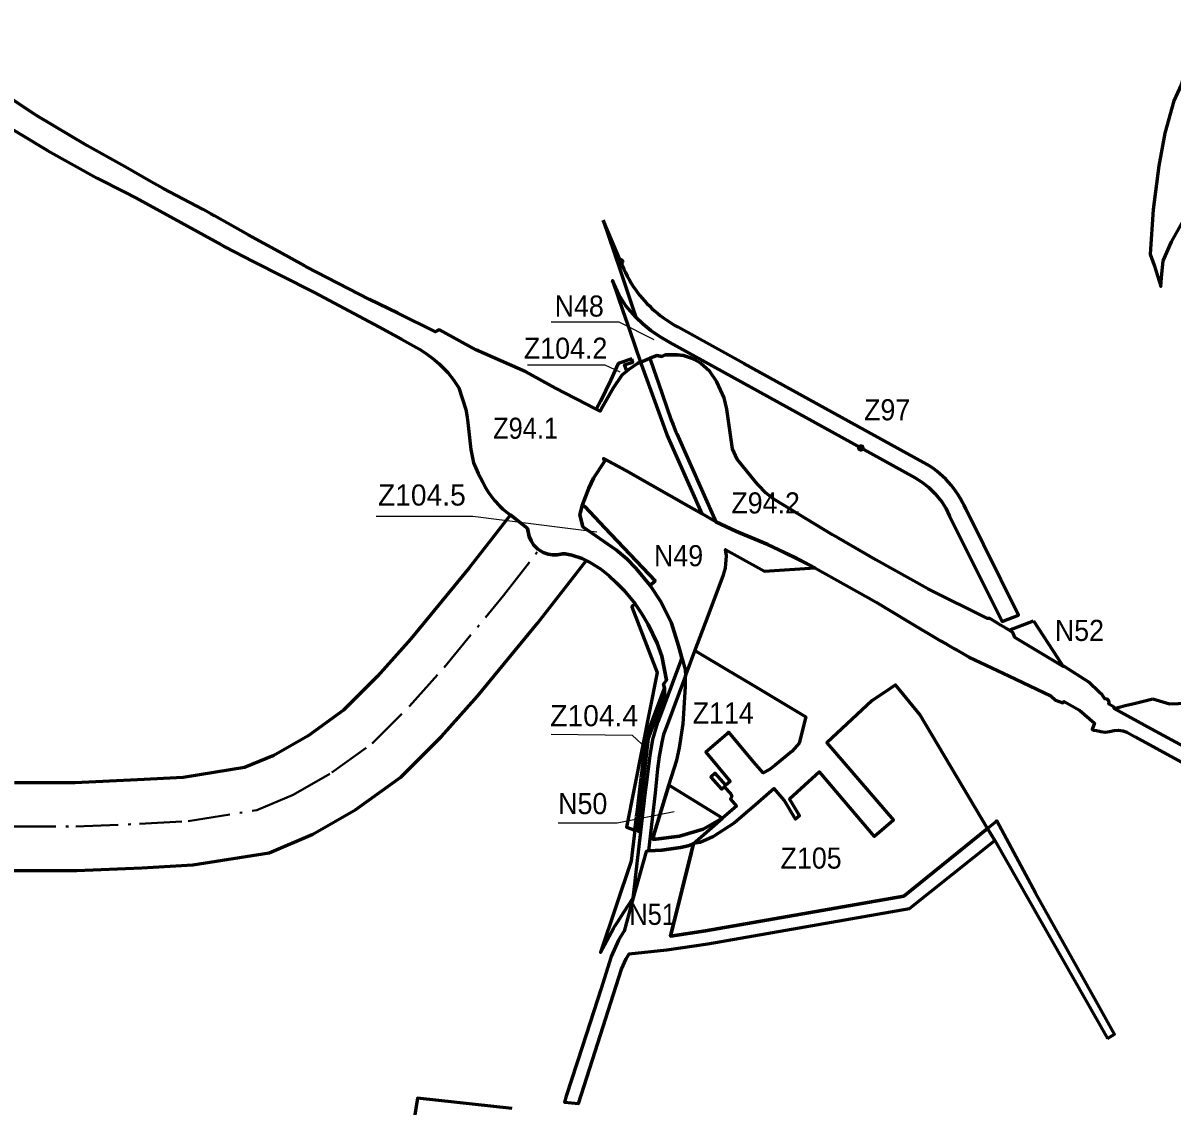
# Model space of a CAD drawing. Extents: x -650277 to -643420, y -1073980 to -1066720.
# Drawn here: x -647259 to -645952, y -1069362 to -1068130 of the extents above; entities that cross this region are included whole.
import ezdxf

# ---------------------------------------------------------------- set-up
doc = ezdxf.new("R2010")
doc.units = 0
doc.header["$LTSCALE"] = 9.6
doc.header["$PDMODE"] = 32
doc.header["$PDSIZE"] = 4.8
doc.linetypes.add('DOT_DASHED', pattern=[7.7, 5, -1.2, 0.3, -1.2])
for name, color, linetype, lineweight in [('13', 7, 'Continuous', 60), ('15', 7, 'Continuous', 60), ('24', 7, 'Continuous', 60), ('30', 7, 'Continuous', 60), ('34', 7, 'Continuous', 60), ('36', 7, 'Continuous', 60), ('42', 7, 'Continuous', 60), ('48', 7, 'Continuous', 60), ('60', 7, 'Continuous', 60), ('62', 7, 'DOT_DASHED', 40), ('63', 7, 'Continuous', 25), ('7', 7, 'Continuous', 60)]:
    doc.layers.add(name, color=color, linetype=linetype, lineweight=lineweight)

msp = doc.modelspace()

# ---------------------------------------------------------------- linework, layer by layer
at = {"layer": '13'}
msp.add_lwpolyline([(-646702.425, -1069364.771), (-646809.879, -1069353.002), (-646842.103, -1069553.182), (-646842.441, -1069555.283), (-646816.615, -1069558.064), (-646754.066, -1069567.993), (-646733.74, -1069471.688)], dxfattribs=at)
at = {"layer": '15'}
for points in [[(-646037.99, -1069242.88), (-646107, -1069119.41), (-646150.87, -1069037.64), (-646152.26, -1069038.76), (-646161.484, -1069046.228), (-646153.307, -1069059.947), (-646025.14, -1069285.394)], [(-646025.14, -1069285.394), (-646017.15, -1069280.19), (-646037.99, -1069242.88)]]:
    msp.add_lwpolyline(points, dxfattribs=at)
at = {"layer": '24'}
for points in [[(-646562.49, -1068790.69), (-646566.34, -1068794.32), (-646537.3, -1068868.95), (-646572.42, -1069044.94), (-646562.61, -1069048.08)], [(-646526.64, -1068877.47), (-646532.16, -1068850.47), (-646537.35, -1068835.56), (-646547.68, -1068814.22), (-646554.8, -1068801.98), (-646562.49, -1068790.69)], [(-646528.92, -1068886.55), (-646530.06, -1068882.16), (-646526.64, -1068877.47)], [(-646562.61, -1069048.08), (-646561.134, -1069035.627), (-646560.79, -1069032.72), (-646560.2, -1069027.69), (-646555.62, -1068988.63), (-646555, -1068983.32), (-646550.3, -1068943.27), (-646537.69, -1068909.82), (-646528.92, -1068886.55)], [(-646555.84, -1069050.22), (-646550.89, -1069007.7), (-646549.81, -1068998.88), (-646549.17, -1068993.71), (-646545.42, -1068963.3), (-646542.16, -1068945.12), (-646536.54, -1068925.95), (-646533.28, -1068917.17), (-646529.44, -1068906.81), (-646529.146, -1068895.373), (-646529.36, -1068895.94), (-646535.79, -1068912.99), (-646547.46, -1068943.97), (-646552.58, -1068987.63), (-646553.2, -1068992.9), (-646556.02, -1069016.97), (-646557.96, -1069033.47), (-646558.145, -1069035.029)], [(-646558.145, -1069035.029), (-646559.8, -1069048.98), (-646555.84, -1069050.22)]]:
    msp.add_lwpolyline(points, dxfattribs=at)
at = {"layer": '30'}
msp.add_line((-646583.49, -1068729.76), (-646571.91, -1068739.54), dxfattribs=at)
for points in [[(-646566.33, -1068512.04), (-646581.64, -1068517.24), (-646590.31, -1068536.69), (-646602.01, -1068560.15), (-646606.59, -1068569.33)], [(-646587.28, -1068545.28), (-646577.07, -1068530.2), (-646572.02, -1068526.07), (-646574.48, -1068518.75), (-646565.04, -1068515.86), (-646566.33, -1068512.04)], [(-646599.75, -1068566.49), (-646587.28, -1068545.28), (-646587.28, -1068545.28)], [(-646606.59, -1068569.33), (-646602.21, -1068571.5), (-646599.75, -1068566.49)], [(-646571.91, -1068739.54), (-646561.5, -1068750.22), (-646545.32, -1068769.89), (-646539.78, -1068764.65), (-646596.93, -1068704.15), (-646619.74, -1068680.15), (-646622.68, -1068678.75), (-646625.35, -1068689.7)], [(-646625.35, -1068689.7), (-646622.01, -1068703.3), (-646583.49, -1068729.76)]]:
    msp.add_lwpolyline(points, dxfattribs=at)
at = {"layer": '34'}
msp.add_lwpolyline([(-646161.484, -1069046.228), (-646238.632, -1068916.799), (-646266.118, -1068883.048), (-646277.268, -1068890.446), (-646292.75, -1068900.72), (-646344.49, -1068948.736), (-646268.528, -1069036.82), (-646290.099, -1069055.423), (-646352.71, -1068981.82), (-646386.936, -1069012.936), (-646375.346, -1069032.07), (-646379.973, -1069035.889), (-646393.09, -1069014.234), (-646404.269, -1069001.033), (-646425.52, -1069019.41), (-646449.418, -1069039.804), (-646474.13, -1069055.83), (-646488.537, -1069062.169), (-646495.89, -1069063.531), (-646500.995, -1069083.812), (-646522.35, -1069168.648), (-646482.211, -1069162.813), (-646256.824, -1069123.414)], close=True, dxfattribs=at)
at = {"layer": '36'}
msp.add_lwpolyline([(-646512.07, -1068954.68), (-646507.91, -1068927.47), (-646505.12, -1068885.31), (-646505.17, -1068872.78), (-646503.24, -1068867.61), (-646494.52, -1068844.29), (-646492.73, -1068845.01), (-646457.86, -1068865.8), (-646430.86, -1068881.89), (-646368.3, -1068919.19), (-646376.02, -1068949.34), (-646383.86, -1068958.24), (-646403.13, -1068974.41), (-646409.67, -1068979.3), (-646416.71, -1068983.21), (-646427.77, -1068970.39), (-646455.78, -1068936.87), (-646458.21, -1068938.99), (-646482.2, -1068959.52), (-646454.21, -1068992.73), (-646459.25, -1068996.98), (-646471.24, -1068983.41), (-646476.35, -1068987.98), (-646464.24, -1069001.49), (-646461.29, -1068998.81), (-646453.48, -1069006.75), (-646452.37, -1069010.01), (-646453.88, -1069013.1), (-646447.2, -1069020.9), (-646462.98, -1069034.61), (-646524, -1068997), (-646514.91, -1068968.48), (-646514.91, -1068968.48)], close=True, dxfattribs=at)
at = {"layer": '42'}
for points in [[(-646561.544, -1068464.842), (-646572.984, -1068451.81), (-646580.625, -1068439.803), (-646588.07, -1068422.96), (-646576.4, -1068457.27), (-646568.87, -1068479.14), (-646556.22, -1068515.84), (-646545.57, -1068511.42), (-646537.71, -1068508.16)], [(-646523.105, -1068493.54), (-646535.245, -1068486.342), (-646544.525, -1068479.79), (-646553.677, -1068472.283), (-646561.544, -1068464.842)], [(-646537.71, -1068508.16), (-646531.9, -1068509.25), (-646528.18, -1068507.58), (-646514.39, -1068507.56), (-646507.4, -1068508.45), (-646498.48, -1068511.26), (-646495.416, -1068512.888), (-646493.511, -1068509.855), (-646523.105, -1068493.54)], [(-646075.56, -1068861.95), (-646130.68, -1068829.21), (-646132.62, -1068823.54), (-646136.99, -1068820.88), (-646109.35, -1068810.23)], [(-646109.35, -1068810.23), (-646081.72, -1068852.51), (-646075.56, -1068861.95)], [(-646017.55, -1068909.75), (-646010.48, -1068907.86), (-646004.88, -1068906.5), (-645994.9, -1068904.1), (-645980.93, -1068900.85), (-645973.36, -1068898.93)], [(-645973.36, -1068898.93), (-645954.59, -1068904.41), (-645944.23, -1068904.13), (-645930.1, -1068902.47), (-645915.61, -1068901.02), (-645902.91, -1068901.43), (-645882.63, -1068905.88), (-645856.26, -1068997.79)], [(-645856.26, -1068997.79), (-645892.77, -1068977.86), (-645933.28, -1068955.74), (-645975.31, -1068932.8), (-646017.55, -1068909.75)]]:
    msp.add_lwpolyline(points, dxfattribs=at)
for points in [[(-646609.7, -1068647.84), (-646615.19, -1068659.11), (-646622.68, -1068678.75), (-646619.74, -1068680.15), (-646596.93, -1068704.15), (-646539.78, -1068764.65), (-646545.32, -1068769.89), (-646532.92, -1068788.95), (-646521.18, -1068812.95), (-646513.27, -1068838.37), (-646505.69, -1068865.56), (-646505.17, -1068872.78), (-646503.24, -1068867.61), (-646494.52, -1068844.29), (-646479.45, -1068804.37), (-646461.92, -1068757.93), (-646459.59, -1068750.19), (-646458.57, -1068736.31), (-646459.54, -1068728.94), (-646453.51, -1068732.3), (-646415.3, -1068753.62), (-646357.87, -1068749.64), (-646411.3, -1068723.11), (-646448.02, -1068707.99), (-646470.65, -1068697.38), (-646486.23, -1068688.54), (-646501.64, -1068679.81), (-646545.73, -1068654.81), (-646573.14, -1068638.98), (-646598.59, -1068625.34), (-646597.4, -1068628.74)], [(-646541.71, -1069054.76), (-646542, -1069059), (-646512, -1069055), (-646485, -1069047), (-646462.98, -1069034.61), (-646524, -1068997)]]:
    msp.add_lwpolyline(points, close=True, dxfattribs=at)
at = {"layer": '48'}
msp.add_lwpolyline([(-645874.15, -1068234.44), (-645917.44, -1068129.99), (-645938.87, -1068193.06), (-645941.41, -1068200.54), (-645949.52, -1068218.72), (-645959.76, -1068255.23), (-645966.56, -1068292.38), (-645973.25, -1068342.08), (-645976.63, -1068393.14), (-645971.94, -1068405.38), (-645964.53, -1068429.83), (-645963.12, -1068415.21), (-645961.7, -1068400.54), (-645952.21, -1068378.95), (-645926.06, -1068332.18), (-645883.87, -1068256.88), (-645880.28, -1068250.47), (-645872.64, -1068238.08)], close=True, dxfattribs=at)
at = {"layer": '60'}
msp.add_line((-646578.881, -1068401.54), (-646598.635, -1068354.436), dxfattribs=at)
for points in [[(-647419.713, -1068138.871), (-647405.71, -1068151.74), (-647372.38, -1068179.01), (-647337.74, -1068205.67), (-647334.62, -1068208.02), (-647307.39, -1068227.44), (-647281.64, -1068244.34), (-647234.11, -1068273.04), (-647230.83, -1068274.93), (-647174.56, -1068306.35), (-647142.788, -1068322.462), (-647130.29, -1068328.8), (-647079.16, -1068357.01), (-647032.91, -1068382.51), (-647029.23, -1068384.46), (-646997.06, -1068401.37), (-646929.56, -1068435.42), (-646927.06, -1068436.66)], [(-646634.37, -1068735.27), (-646622.62, -1068739.32), (-646613.44, -1068743.65), (-646601.86, -1068751.01), (-646592.53, -1068758.66), (-646583.98, -1068766.42), (-646575.28, -1068775.04), (-646562.49, -1068790.69), (-646554.8, -1068801.98), (-646547.68, -1068814.22), (-646537.35, -1068835.56), (-646532.16, -1068850.47), (-646526.64, -1068877.47), (-646530.06, -1068882.16), (-646528.92, -1068886.55), (-646529.44, -1068906.81), (-646510.56, -1068855.86), (-646509.323, -1068852.529), (-646513.27, -1068838.37), (-646521.18, -1068812.95), (-646532.92, -1068788.95), (-646545.32, -1068769.89), (-646561.5, -1068750.22), (-646571.91, -1068739.54), (-646583.49, -1068729.76), (-646622.01, -1068703.3), (-646625.35, -1068689.7), (-646622.68, -1068678.75), (-646615.19, -1068659.11), (-646609.7, -1068647.84), (-646597.4, -1068628.74), (-646596.28, -1068626.52), (-646596.28, -1068626.52), (-646573.14, -1068638.98), (-646545.73, -1068654.81), (-646545.73, -1068654.81), (-646501.64, -1068679.81), (-646486.23, -1068688.54), (-646526.1, -1068598.55), (-646555, -1068519.38), (-646555, -1068519.38), (-646556.22, -1068515.84), (-646559.72, -1068517.29), (-646569.61, -1068524.1), (-646572.02, -1068526.07), (-646577.07, -1068530.2), (-646587.28, -1068545.28), (-646599.75, -1068566.49), (-646602.21, -1068571.5), (-646606.59, -1068569.33), (-646620.94, -1068561.96), (-646625.86, -1068559.47), (-646631.18, -1068556.77), (-646653.21, -1068545.58), (-646686.84, -1068526.89), (-646686.84, -1068526.89), (-646743.69, -1068501.76), (-646785.05, -1068479.12), (-646787.55, -1068480.36), (-646789.49, -1068481.31), (-646832.29, -1068460.04), (-646864.48, -1068444.64), (-646936.47, -1068407.23), (-646938.95, -1068405.8), (-646967.64, -1068390), (-647002.71, -1068371.09), (-647040.77, -1068349.4), (-647044.93, -1068347.08), (-647053.75, -1068342.11), (-647099.2, -1068318.27), (-647112.813, -1068310.564), (-647142.41, -1068293.81), (-647186.26, -1068269.45), (-647243.39, -1068235.26), (-647246.8, -1068233.08), (-647295.47, -1068201.09)], [(-646598.635, -1068354.436), (-646579.62, -1068411.29), (-646564.78, -1068455.41), (-646561.544, -1068464.842)], [(-646927.06, -1068436.66), (-646854.18, -1068475.8), (-646828.2, -1068489.61), (-646807.82, -1068501.17), (-646799.79, -1068506.39), (-646790.66, -1068513.24), (-646785.34, -1068517.77), (-646779.93, -1068522.9), (-646775.44, -1068527.74), (-646768.95, -1068535.8), (-646763.1, -1068545.18), (-646754.92, -1068569.81), (-646753.35, -1068578.6), (-646752.59, -1068584.55), (-646749.35, -1068615.18), (-646746.32, -1068630.23), (-646740.91, -1068642.34), (-646735.62, -1068652.21), (-646732.25, -1068659.06), (-646729.34, -1068663.94), (-646722.6, -1068673.11), (-646716.39, -1068679.8), (-646716.39, -1068679.8), (-646712.93, -1068683), (-646684.7, -1068704.95), (-646682.98, -1068714.07), (-646680.88, -1068719.28), (-646678.08, -1068723.7), (-646673.16, -1068728.69), (-646667.17, -1068732.38), (-646667.17, -1068732.38), (-646661.5, -1068734.35), (-646656.47, -1068735.13), (-646651.21, -1068734.99), (-646645.18, -1068733.91), (-646642.04, -1068733.74), (-646634.37, -1068735.27)], [(-646561.544, -1068464.842), (-646553.677, -1068472.283), (-646544.525, -1068479.79), (-646535.245, -1068486.342), (-646523.105, -1068493.54), (-646493.511, -1068509.855), (-646305.678, -1068613.404)], [(-646234.342, -1068629.893), (-646234.342, -1068629.892), (-646438.626, -1068517.274), (-646513.45, -1068476.025), (-646513.567, -1068475.963)], [(-646337.93, -1068712.4), (-646404.83, -1068671.52), (-646413.45, -1068664.71), (-646422.32, -1068655.58), (-646425.11, -1068652.37), (-646446.54, -1068626.14), (-646451.82, -1068614.31), (-646458.03, -1068569.26), (-646461.14, -1068556.34), (-646469.51, -1068538.15), (-646477.41, -1068526.45), (-646487.92, -1068516.87), (-646498.48, -1068511.26), (-646507.4, -1068508.45), (-646514.39, -1068507.56), (-646528.18, -1068507.58), (-646531.9, -1068509.25), (-646537.71, -1068508.16), (-646545.57, -1068511.42), (-646541.06, -1068524.58), (-646535.84, -1068539.8), (-646521.81, -1068580.69), (-646519.14, -1068587.06), (-646516.07, -1068595.08), (-646515.09, -1068597.29), (-646470.65, -1068697.38), (-646448.02, -1068707.99), (-646444.51, -1068709.64), (-646411.3, -1068723.11), (-646380.94, -1068737.81), (-646357.87, -1068749.64), (-646297.08, -1068783.8), (-646288.37, -1068789.04), (-646251.73, -1068811.04), (-646214.92, -1068832.85), (-646208.7, -1068836.39), (-646205.48, -1068838.23), (-646199.24, -1068841.79), (-646195.52, -1068843.92), (-646182.57, -1068851.3)], [(-646305.678, -1068613.404), (-646243.997, -1068647.407), (-646236.707, -1068651.891), (-646228.691, -1068658.051), (-646221.348, -1068665.144), (-646213.659, -1068674.696), (-646209.179, -1068681.795), (-646204.654, -1068690.937), (-646145.083, -1068810.83), (-646126.317, -1068803.654), (-646186.371, -1068682.825)], [(-647270.522, -1069094.255), (-647197.498, -1069094.255), (-647123.648, -1069091.043), (-647065.688, -1069087.73), (-646978.92, -1069073.93), (-646929.186, -1069052.925), (-646880.163, -1069024.903), (-646829.104, -1068987.917), (-646782.784, -1068941.581), (-646741.85, -1068895.719), (-646673.05, -1068812.491), (-646618.655, -1068742.359), (-646617.991, -1068741.503), (-646622.62, -1068739.32), (-646634.37, -1068735.27), (-646642.04, -1068733.74), (-646645.18, -1068733.91), (-646651.21, -1068734.99), (-646656.47, -1068735.13), (-646661.5, -1068734.35), (-646667.17, -1068732.38), (-646673.16, -1068728.69), (-646678.08, -1068723.7), (-646680.88, -1068719.28), (-646682.98, -1068714.07), (-646684.7, -1068704.95), (-646704.316, -1068689.698), (-646725.374, -1068716.786), (-646751.116, -1068749.975), (-646817.718, -1068830.545), (-646855.506, -1068872.883), (-646894.206, -1068911.595), (-646934.465, -1068940.759), (-646973.61, -1068963.135), (-647006.63, -1068977.08), (-647076.422, -1068988.18), (-647128.674, -1068991.167), (-647199.672, -1068994.255), (-647268.348, -1068994.255)], [(-645933.28, -1068955.74), (-645975.31, -1068932.8), (-646017.55, -1068909.75), (-646017.39, -1068908.42), (-646023.56, -1068905.05), (-646023.13, -1068903.12), (-646023.92, -1068900.73), (-646025.57, -1068899.39), (-646028.18, -1068898.89), (-646031.31, -1068894.32), (-646034.65, -1068891.12), (-646046.48, -1068879.92), (-646074.78, -1068861.51), (-646075.56, -1068861.95), (-646130.68, -1068829.21), (-646132.62, -1068823.54), (-646136.99, -1068820.88), (-646140.73, -1068818.61), (-646146.85, -1068814.88), (-646150.26, -1068812.81), (-646159.1, -1068807.43), (-646161.45, -1068807.54), (-646229.44, -1068773.53), (-646288.59, -1068740.88), (-646331.26, -1068716.25), (-646337.93, -1068712.4)], [(-646182.57, -1068851.3), (-646137.23, -1068872.6), (-646089.63, -1068895.5), (-646084.1, -1068900.51), (-646076.09, -1068903.48), (-646074.51, -1068901.9), (-646057.13, -1068911.62), (-646039.84, -1068926.67), (-646042.5, -1068933.91), (-646040.65, -1068934.59), (-646037.5, -1068934.7), (-646032.61, -1068936.1), (-646027.69, -1068936.6), (-646022.77, -1068936.12), (-646017.6, -1068934.89), (-646012.64, -1068934.34), (-646007.7, -1068935.18), (-646002.95, -1068936.95), (-645993.5, -1068942.1), (-645940.77, -1068970.74)], [(-646505.17, -1068872.78), (-646526.81, -1068930.69), (-646530.08, -1068939.43), (-646532.13, -1068948), (-646535.13, -1068964.38), (-646537.02, -1068978.44), (-646539.77, -1069006.25)], [(-646524, -1068997), (-646514.91, -1068968.48), (-646514.91, -1068968.48), (-646512.07, -1068954.68), (-646507.91, -1068927.47), (-646505.12, -1068885.31), (-646505.17, -1068872.78)], [(-646462.98, -1069034.61), (-646485, -1069047), (-646512, -1069055), (-646542, -1069059), (-646541.71, -1069054.76), (-646524, -1068997)], [(-646539.77, -1069006.25), (-646539.77, -1069006.25), (-646547.412, -1069071.71)], [(-646547.412, -1069071.71), (-646532, -1069071), (-646511, -1069068), (-646502, -1069066), (-646496.317, -1069063.61), (-646462.98, -1069034.61)]]:
    msp.add_lwpolyline(points, dxfattribs=at)
msp.add_lwpolyline([(-646582.46, -1069152.81), (-646575.4, -1069141.46), (-646564.54, -1069125.08), (-646562.35, -1069106.21), (-646561.88, -1069102.18), (-646555.84, -1069050.22), (-646555.84, -1069050.22), (-646559.8, -1069048.98), (-646562.61, -1069048.08), (-646566.82, -1069083.62), (-646601.82, -1069187.25), (-646586.97, -1069160.06), (-646585.42, -1069157.56), (-646583.89, -1069155.1), (-646582.46, -1069152.81)], close=True, dxfattribs=at)
for centre, radius, start, end in [((-646447.332, -1068351.964), 140.58, 200.6496, 215.36619), ((-646447.332, -1068351.964), 140.58, 215.36631, 241.891), ((-646287.447, -1068726.224), 110, 23.23727, 61.13296)]:
    msp.add_arc(centre, radius, start, end, dxfattribs=at)
for p in [(-646578.881, -1068401.54), (-646305.678, -1068613.404)]:
    msp.add_point(p, dxfattribs=at)
at = {"layer": '62'}
msp.add_lwpolyline([(-647953.174, -1069007.503), (-647892.914, -1069003.305), (-647829.936, -1069000.155), (-647777.98, -1069001.73), (-647703.981, -1069006.455), (-647634.706, -1069014.33), (-647507.176, -1069026.93), (-647422.156, -1069034.805), (-647341.859, -1069041.105), (-647269.435, -1069044.255), (-647198.585, -1069044.255), (-647126.161, -1069041.105), (-647071.055, -1069037.955), (-646992.775, -1069025.505), (-646951.398, -1069008.03), (-646907.314, -1068982.831), (-646861.655, -1068949.756), (-646819.145, -1068907.232), (-646779.784, -1068863.132), (-646712.083, -1068781.233), (-646669.79, -1068726.705)], dxfattribs=at)
at = {"layer": '63'}
for points in [[(-646658, -1068470), (-646581, -1068470), (-646541, -1068490)], [(-646685, -1068519), (-646597, -1068519), (-646580, -1068527)], [(-646857, -1068691), (-646747, -1068691), (-646606, -1068709)], [(-646658, -1068939), (-646566, -1068940), (-646550, -1068955)], [(-646650, -1069040), (-646583, -1069040), (-646518, -1069027)]]:
    msp.add_lwpolyline(points, dxfattribs=at)
at = {"layer": '7'}
msp.add_lwpolyline([(-646522.35, -1069168.648), (-646495.89, -1069063.531), (-646496.317, -1069063.61), (-646496.317, -1069063.61), (-646502, -1069066), (-646511, -1069068), (-646532, -1069071), (-646547.412, -1069071.71), (-646549.91, -1069072.542), (-646564.54, -1069125.08), (-646564.605, -1069125.271), (-646574.978, -1069163.017), (-646574.978, -1069163.017), (-646574.33, -1069162.04), (-646575.87, -1069164.54), (-646581.29, -1069173.32), (-646589.56, -1069192.07), (-646601.41, -1069229.34), (-646613.6, -1069267.04), (-646627.59, -1069310.34), (-646628.66, -1069313.66), (-646640.715, -1069350.951), (-646642.89, -1069357.68), (-646626.774, -1069359.349), (-646611.107, -1069309.68), (-646577.878, -1069206.485), (-646572.586, -1069194.485), (-646569.114, -1069188.86), (-646526.31, -1069184.381), (-646479.84, -1069177.626), (-646250.409, -1069137.52), (-646153.307, -1069059.947), (-646161.484, -1069046.228), (-646256.824, -1069123.414), (-646482.211, -1069162.813)], close=True, dxfattribs=at)

# ---------------------------------------------------------------- texts
at = {"layer": '63'}
for s, width, p in [('N48', 0.95, (-646654, -1068464)), ('Z104.2', 0.95, (-646689, -1068512)), ('Z97', 0.95, (-646302, -1068582)), ('Z94.1', 0.9, (-646724, -1068603)), ('Z94.2', 0.95, (-646453, -1068688)), ('N49', 0.95, (-646541, -1068748)), ('N52', 0.95, (-646085, -1068833)), ('Z114', 0.95, (-646497, -1068927)), ('N50', 0.95, (-646650, -1069030)), ('Z105', 0.95, (-646397, -1069092)), ('N51', 0.9, (-646569, -1069156))]:
    msp.add_text(s, height=24, dxfattribs=dict(at, width=width)).set_placement(p)
for s, p in [('Z104.5', (-646855, -1068679)), ('Z104.4', (-646659, -1068930))]:
    msp.add_text(s, height=24, dxfattribs=at).set_placement(p)

doc.saveas('drawing.dxf')
